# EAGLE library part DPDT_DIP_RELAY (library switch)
RELAY DPDT Purchased from all electronics part number: rly=625 Made by Kest Datasheet at http://www.kestparts.com/datasheets/relays/KS2EMseries.pdf
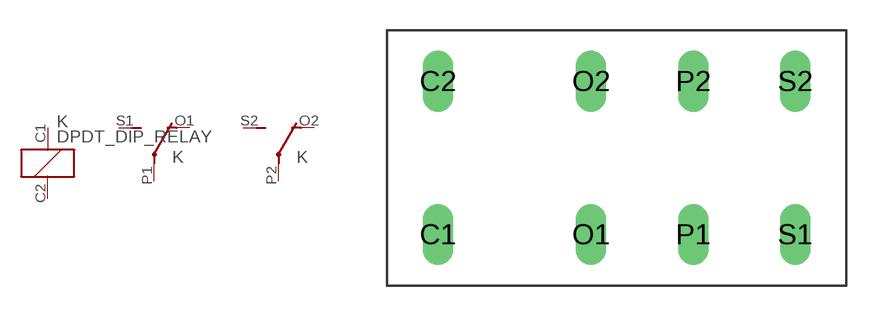
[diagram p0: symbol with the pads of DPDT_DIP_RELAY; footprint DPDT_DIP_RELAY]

Designator prefix K; gates 1=K 2=U 3=U

## DPDT_DIP_RELAY  [DPDT_DIP_RELAY]
C1  1:1  pas
C2  1:2  pas
O1  2:O  pas
O2  3:O  pas
P1  2:P  pas
P2  3:P  pas
S1  2:S  pas
S2  3:S  pas

## Footprint DPDT_DIP_RELAY (pad centres in mm)
RELAY 2 x switch, Omron
drill 1.016 long: C1 -2.54,7.62; C2 -2.54,15.24; O1 5.08,7.62; O2 5.08,15.24; P1 10.16,7.62; P2 10.16,15.24; S1 15.24,7.62; S2 15.24,15.24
